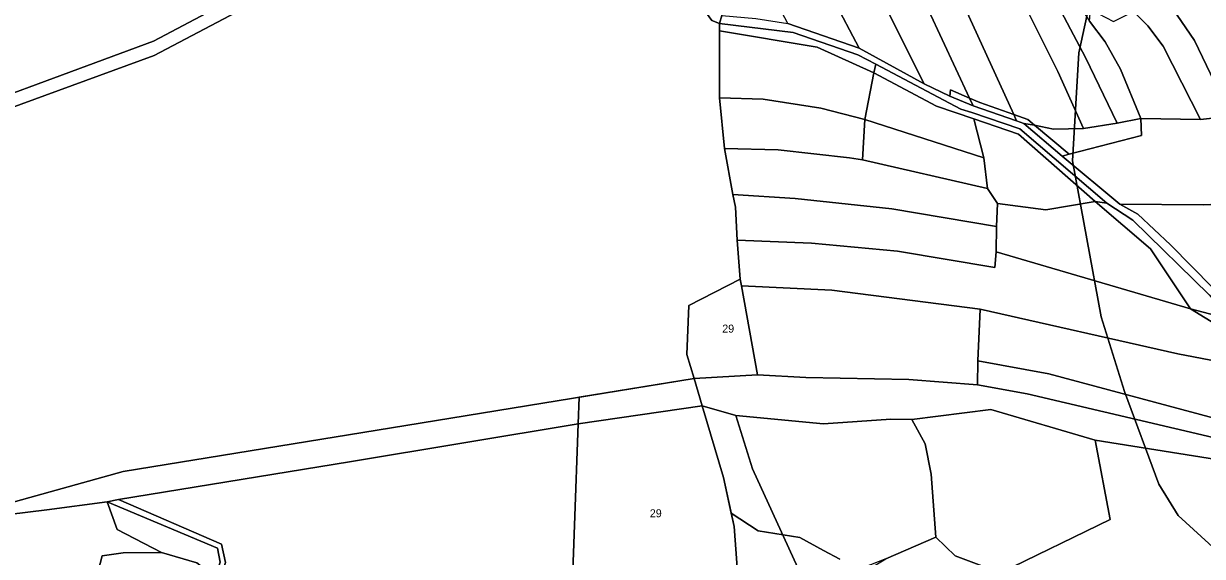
# Model space of a CAD drawing. Extents: x -521261 to -517465, y -1182764 to -1179456.
# Drawn here: x -520500 to -519763, y -1180889 to -1180556 of the extents above; entities that cross this region are included whole.
import ezdxf

# ---------------------------------------------------------------- set-up
doc = ezdxf.new("R2010")
doc.units = 0
for name, color, linetype in [('95560013', 7, 'Continuous'), ('95610013', 7, 'Continuous'), ('95620013', 7, 'Continuous'), ('95640013', 7, 'Continuous'), ('95660013', 7, 'Continuous')]:
    doc.layers.add(name, color=color, linetype=linetype)

msp = doc.modelspace()

# ---------------------------------------------------------------- linework, layer by layer
at = {"layer": '95560013'}
for points in [[(-519926.76, -1180525.85), (-519920.55, -1180526.74), (-519881.21, -1180613), (-519902.42, -1180605.56), (-519908.84, -1180602.74), (-519942.92, -1180529.19)], [(-519879.66, -1180533.88), (-519853.6, -1180586.17), (-519837.56, -1180621.72), (-519856.32, -1180622.11), (-519868.13, -1180619.64), (-519872.32, -1180616.13), (-519881.21, -1180613), (-519920.55, -1180526.74)], [(-519966.95, -1180534.21), (-519937.24, -1180593.79), (-519977.79, -1180571.45), (-519993.87, -1180540.91)], [(-519942.92, -1180529.19), (-519908.84, -1180602.74), (-519920.76, -1180597.55), (-519921.12, -1180601.42), (-519937.24, -1180593.79), (-519966.95, -1180534.21)], [(-519857.1, -1180537.86), (-519836.41, -1180577.26), (-519816.49, -1180618.3), (-519837.56, -1180621.72), (-519853.6, -1180586.17), (-519879.66, -1180533.88)], [(-519993.87, -1180540.91), (-519977.79, -1180571.45), (-520022.38, -1180556.11), (-520025.98, -1180548.95)], [(-519843.08, -1180540.27), (-519833.76, -1180554.68), (-519824.12, -1180567.61), (-519814.57, -1180584.59), (-519801.81, -1180615.54), (-519816.49, -1180618.3), (-519836.41, -1180577.26), (-519857.1, -1180537.86)], [(-520065.13, -1180560.74), (-520004.02, -1180570.89), (-519968.52, -1180586.94), (-519974.16, -1180616.17), (-520001.62, -1180608.95), (-520037.78, -1180603.34), (-520065.1, -1180602.48)], [(-519968.52, -1180586.94), (-519929.38, -1180607.81), (-519906.15, -1180615.63), (-519899.83, -1180640.03), (-519974.16, -1180616.17)], [(-520065.1, -1180602.48), (-520037.78, -1180603.34), (-520001.62, -1180608.95), (-519974.16, -1180616.17), (-519975.68, -1180641.23), (-519983.78, -1180640.12), (-520028.41, -1180635.13), (-520061.92, -1180634.28)], [(-519878.11, -1180625.31), (-519830.39, -1180667.29), (-519861.08, -1180672.47), (-519891.43, -1180668.65), (-519897.52, -1180659.28), (-519899.83, -1180640.03), (-519906.15, -1180615.63)], [(-519816.49, -1180618.3), (-519801.81, -1180615.54), (-519801.28, -1180626.06), (-519846.5, -1180637.75), (-519868.13, -1180619.64), (-519856.32, -1180622.11), (-519837.56, -1180621.72)], [(-519974.16, -1180616.17), (-519899.83, -1180640.03), (-519897.52, -1180659.28), (-519975.68, -1180641.23)], [(-520061.92, -1180634.28), (-520028.41, -1180635.13), (-519983.78, -1180640.12), (-519975.68, -1180641.23), (-519897.52, -1180659.28), (-519891.43, -1180668.65), (-519891.89, -1180682.93), (-519957.26, -1180672.03), (-520017.65, -1180665.4), (-520056.64, -1180662.89)], [(-520017.65, -1180665.4), (-519957.26, -1180672.03), (-519891.89, -1180682.93), (-519892.08, -1180698.83), (-519893.06, -1180708.57), (-519953.8, -1180698.37), (-520007.56, -1180693.31), (-520054.03, -1180691.48), (-520055.03, -1180670.89), (-520056.64, -1180662.89)], [(-519861.08, -1180672.47), (-519830.39, -1180667.29), (-519795.72, -1180696.92), (-519770.67, -1180734.47), (-519892.08, -1180698.83), (-519891.89, -1180682.93), (-519891.43, -1180668.65)], [(-520007.56, -1180693.31), (-519953.8, -1180698.37), (-519893.06, -1180708.57), (-519892.08, -1180698.83), (-519770.67, -1180734.47), (-519752.39, -1180745.68), (-519753.69, -1180767.33), (-519778.68, -1180762.64), (-519902.11, -1180734.59), (-519994.76, -1180722.85), (-520051.3, -1180720.05), (-520052.16, -1180715.87), (-520054.03, -1180691.48)], [(-520051.3, -1180720.05), (-519994.76, -1180722.85), (-519902.11, -1180734.59), (-519903.71, -1180766.9), (-519903.89, -1180781.93), (-519946.67, -1180778.48), (-520011.06, -1180777.29), (-520041.21, -1180775.69)], [(-519902.11, -1180734.59), (-519778.68, -1180762.64), (-519753.69, -1180767.33), (-519755.86, -1180802.82), (-519859.26, -1180774.99), (-519903.71, -1180766.9)], [(-519903.71, -1180766.9), (-519859.26, -1180774.99), (-519755.86, -1180802.82), (-519756.54, -1180814.92), (-519872.76, -1180787.48), (-519903.89, -1180781.93)]]:
    msp.add_lwpolyline(points, close=True, dxfattribs=at)
at = {"layer": '95610013'}
for points in [[(-519787.11, -1180538.74), (-519768.22, -1180566.74), (-519755.66, -1180592.71), (-519747.7, -1180614.18), (-519764.44, -1180616.17), (-519787.86, -1180570.19), (-519797.31, -1180557.63), (-519806.32, -1180548.59), (-519809.29, -1180545.42), (-519790.04, -1180534.46)], [(-519762, -1180533.09), (-519756.87, -1180539.77), (-519746.34, -1180566.13), (-519737.99, -1180583.64), (-519734.67, -1180590.12), (-519723.97, -1180611.09), (-519747.7, -1180614.18), (-519755.66, -1180592.71), (-519768.22, -1180566.74), (-519787.11, -1180538.74), (-519764.17, -1180530.48)], [(-519833.18, -1180547.3), (-519818.8, -1180554.91), (-519806.32, -1180548.59), (-519797.31, -1180557.63), (-519787.86, -1180570.19), (-519764.44, -1180616.17), (-519801.81, -1180615.54), (-519814.57, -1180584.59), (-519824.12, -1180567.61), (-519833.76, -1180554.68)], [(-519764.44, -1180616.17), (-519747.7, -1180614.18), (-519717.59, -1180667.43), (-519762.68, -1180669.48), (-519814.85, -1180668.94), (-519850.9, -1180639.04), (-519846.5, -1180637.75), (-519801.28, -1180626.06), (-519801.81, -1180615.54)], [(-519717.59, -1180667.43), (-519708.21, -1180689.61), (-519692.2, -1180746.98), (-519697.59, -1180747.55), (-519712.21, -1180749.16), (-519717.76, -1180748.91), (-519756.77, -1180721.21), (-519783.25, -1180694.48), (-519803.71, -1180675.31), (-519814.85, -1180668.94), (-519762.68, -1180669.48)], [(-520413.63, -1180886.67), (-520391.57, -1180893.1), (-520380.19, -1180902.05), (-520402.93, -1180971), (-520404.76, -1180971.74), (-520414.45, -1180949.49), (-520429.91, -1180949.77), (-520466.27, -1180947.66), (-520450.85, -1180888.84), (-520437.74, -1180886.84)]]:
    msp.add_lwpolyline(points, close=True, dxfattribs=at)
at = {"layer": '95620013'}
for points in [[(-520561.44, -1180628.41), (-520418.21, -1180576.2), (-520359.3, -1180545.16), (-520250.11, -1180487.13), (-520218.6, -1180468.97), (-520194.59, -1180462.72), (-520147.74, -1180469.38), (-520127.48, -1180474.4), (-520069.86, -1180554.25), (-520065.03, -1180556.21), (-520065.13, -1180560.74), (-520065.1, -1180602.48), (-520061.92, -1180634.28), (-520056.64, -1180662.89), (-520055.03, -1180670.89), (-520054.03, -1180691.48), (-520052.16, -1180715.87), (-520084.17, -1180732.28), (-520085.42, -1180763.05), (-520080.76, -1180777.95), (-520260.96, -1180807.27), (-520437.72, -1180836.09), (-520517.73, -1180858.28)], [(-520267.22, -1180487.01), (-520418.64, -1180567.25), (-520579.89, -1180626.79)]]:
    msp.add_lwpolyline(points, dxfattribs=at)
for points in [[(-520153.4, -1180806.35), (-520157.92, -1180932.93), (-520196.52, -1180926.36), (-520199.57, -1180927.79), (-520202.96, -1180943.49), (-520212.94, -1180946.42), (-520219.04, -1180948.87), (-520227.61, -1180952.85), (-520260.64, -1180952.48), (-520300.29, -1180947.88), (-520344.99, -1180950.96), (-520344.3, -1180943.96), (-520347.18, -1180922.08), (-520360, -1180918.29), (-520377.28, -1180904.27), (-520373.63, -1180892.94), (-520376.27, -1180881.41), (-520440.58, -1180853.57), (-520296.21, -1180829.93)], [(-520447.63, -1180855.08), (-520441.44, -1180872.23), (-520413.63, -1180886.67), (-520437.74, -1180886.84), (-520450.85, -1180888.84), (-520466.27, -1180947.66), (-520479.73, -1180952.5), (-520490.67, -1180954.03), (-520505.09, -1180945.85), (-520508.85, -1180907.38), (-520510.51, -1180896.3), (-520514.96, -1180895.18), (-520522.73, -1180871.37), (-520521.14, -1180864.38), (-520485.24, -1180860)], [(-520441.44, -1180872.23), (-520447.63, -1180855.08), (-520378.72, -1180883.92), (-520376.96, -1180892.63), (-520380.19, -1180902.05), (-520391.57, -1180893.1), (-520413.63, -1180886.67)]]:
    msp.add_lwpolyline(points, close=True, dxfattribs=at)
at = {"layer": '95640013'}
for points in [[(-520579.89, -1180626.79), (-520418.64, -1180567.25), (-520267.22, -1180487.01), (-520224.7, -1180457.68), (-520218.82, -1180457.68), (-520195.07, -1180457.1), (-520147.94, -1180463.58), (-520122.8, -1180471.55), (-520063.47, -1180551.19), (-520042.35, -1180553.05), (-520022.38, -1180556.11), (-519977.79, -1180571.45), (-519937.24, -1180593.79), (-519921.12, -1180601.42), (-519906.63, -1180607.48), (-519879.5, -1180616.96), (-519874.81, -1180618.65), (-519850.9, -1180639.04), (-519814.85, -1180668.94), (-519803.71, -1180675.31), (-519783.25, -1180694.48), (-519756.77, -1180721.21)], [(-519759.06, -1180725.67), (-519806.67, -1180679.04), (-519823.08, -1180668.31), (-519877.33, -1180621.85), (-519907.42, -1180611.79), (-519914.26, -1180609.63), (-519967.45, -1180581.52), (-519978.62, -1180575.67), (-520019.07, -1180561.78), (-520065.03, -1180556.21), (-520069.86, -1180554.25), (-520127.48, -1180474.4), (-520147.74, -1180469.38), (-520194.59, -1180462.72), (-520218.6, -1180468.97), (-520250.11, -1180487.13), (-520359.3, -1180545.16), (-520418.21, -1180576.2), (-520561.44, -1180628.41)], [(-519762.65, -1180910.2), (-519780.23, -1180911.25), (-519803.42, -1180920.5), (-519828.85, -1180932.73), (-519852.45, -1180947.32), (-519857.68, -1180946.63), (-519859.11, -1180944.04), (-519877.24, -1180908.93), (-519889.4, -1180899.42), (-519820.97, -1180866.09), (-519830.34, -1180816.46), (-519754.46, -1180828.52)]]:
    msp.add_lwpolyline(points, dxfattribs=at)
for points in [[(-520065.03, -1180556.21), (-520019.07, -1180561.78), (-519978.62, -1180575.67), (-519967.45, -1180581.52), (-519968.52, -1180586.94), (-520004.02, -1180570.89), (-520065.13, -1180560.74)], [(-519968.52, -1180586.94), (-519967.45, -1180581.52), (-519914.26, -1180609.63), (-519907.42, -1180611.79), (-519877.33, -1180621.85), (-519823.08, -1180668.31), (-519830.39, -1180667.29), (-519878.11, -1180625.31), (-519906.15, -1180615.63), (-519929.38, -1180607.81)], [(-519920.76, -1180597.55), (-519908.84, -1180602.74), (-519906.63, -1180607.48), (-519921.12, -1180601.42)], [(-519902.42, -1180605.56), (-519881.21, -1180613), (-519879.5, -1180616.96), (-519906.63, -1180607.48), (-519908.84, -1180602.74)], [(-519872.32, -1180616.13), (-519868.13, -1180619.64), (-519874.81, -1180618.65), (-519879.5, -1180616.96), (-519881.21, -1180613)], [(-519874.81, -1180618.65), (-519868.13, -1180619.64), (-519846.5, -1180637.75), (-519850.9, -1180639.04)], [(-519830.39, -1180667.29), (-519823.08, -1180668.31), (-519806.67, -1180679.04), (-519759.06, -1180725.67), (-519746.21, -1180740.96), (-519770.67, -1180734.47), (-519795.72, -1180696.92)], [(-520052.16, -1180715.87), (-520051.3, -1180720.05), (-520041.21, -1180775.69), (-520080.76, -1180777.95), (-520085.42, -1180763.05), (-520084.17, -1180732.28)], [(-519770.67, -1180734.47), (-519746.21, -1180740.96), (-519730.77, -1180757.97), (-519752.39, -1180745.68)], [(-520011.06, -1180777.29), (-519946.67, -1180778.48), (-519903.89, -1180781.93), (-519872.76, -1180787.48), (-519756.54, -1180814.92), (-519712.86, -1180822.81), (-519712.22, -1180850.29), (-519724.46, -1180847.03), (-519724.95, -1180841.1), (-519739.68, -1180829.86), (-519754.46, -1180828.52), (-519830.34, -1180816.46), (-519895.53, -1180797.23), (-519944.79, -1180803.65), (-519957.95, -1180803.28), (-520000.15, -1180806.24), (-520054.72, -1180801.07), (-520075.86, -1180795.03), (-520080.76, -1180777.95), (-520041.21, -1180775.69)], [(-520080.76, -1180777.95), (-520075.86, -1180795.03), (-520153.4, -1180806.35), (-520296.21, -1180829.93), (-520440.58, -1180853.57), (-520447.63, -1180855.08), (-520485.24, -1180860), (-520521.14, -1180864.38), (-520532.28, -1180856.24), (-520565.24, -1180830.11), (-520584.27, -1180823.22), (-520567.99, -1180819.26), (-520561.06, -1180820.59), (-520517.73, -1180858.28), (-520437.72, -1180836.09), (-520260.96, -1180807.27)], [(-520075.86, -1180795.03), (-520062.43, -1180839.83), (-520055.89, -1180870.36), (-520052.08, -1180921.54), (-520063.22, -1180921.42), (-520109.27, -1180947.28), (-520129.83, -1180952.33), (-520148.15, -1180951.58), (-520165.05, -1180947.64), (-520157.92, -1180932.93), (-520153.4, -1180806.35)], [(-520075.86, -1180795.03), (-520054.72, -1180801.07), (-520044.44, -1180834.39), (-520009.14, -1180911.27), (-520027.64, -1180915.53), (-520052.08, -1180921.54), (-520055.89, -1180870.36), (-520062.43, -1180839.83)], [(-519944.79, -1180803.65), (-519895.53, -1180797.23), (-519830.34, -1180816.46), (-519820.97, -1180866.09), (-519889.4, -1180899.42), (-519917.75, -1180888.83), (-519929.88, -1180877.1), (-519932.71, -1180837.71), (-519936.58, -1180818.81)], [(-519957.95, -1180803.28), (-519944.79, -1180803.65), (-519936.58, -1180818.81), (-519932.71, -1180837.71), (-519929.88, -1180877.1), (-519961.16, -1180890.66), (-519989.88, -1180901.85), (-520009.14, -1180911.27), (-520044.44, -1180834.39), (-520054.72, -1180801.07), (-520000.15, -1180806.24)], [(-520447.63, -1180855.08), (-520440.58, -1180853.57), (-520376.27, -1180881.41), (-520373.63, -1180892.94), (-520377.28, -1180904.27), (-520380.19, -1180902.05), (-520376.96, -1180892.63), (-520378.72, -1180883.92)], [(-519917.75, -1180888.83), (-519889.4, -1180899.42), (-519877.24, -1180908.93), (-519859.11, -1180944.04), (-519857.68, -1180946.63), (-519913.83, -1180971.76), (-519924.17, -1180970.12), (-519933.74, -1180965.29), (-519970.64, -1180971.8), (-520002.63, -1180979.16), (-520027.64, -1180915.53), (-520009.14, -1180911.27), (-519994.33, -1180910.58), (-519961.16, -1180890.66), (-519929.88, -1180877.1)]]:
    msp.add_lwpolyline(points, close=True, dxfattribs=at)
at = {"layer": '95660013'}
for points in [[(-519739, -1180397), (-519775, -1180405), (-519786.5, -1180414), (-519802.5, -1180437), (-519821, -1180484.5), (-519840.5, -1180574.5), (-519844.5, -1180642), (-519826.5, -1180739.5), (-519812, -1180786), (-519790.5, -1180844), (-519778.5, -1180863.5), (-519754.5, -1180885.5)], [(-519754.5, -1180885.5), (-519778.5, -1180863.5), (-519790.5, -1180844), (-519812, -1180786), (-519826.5, -1180739.5), (-519844.5, -1180642), (-519840.5, -1180574.5), (-519821, -1180484.5), (-519802.5, -1180437), (-519786.5, -1180414), (-519775, -1180405), (-519739, -1180397)], [(-520063.47, -1180551.19), (-520065.03, -1180556.21), (-520065.13, -1180560.74), (-520065.1, -1180602.48), (-520061.92, -1180634.28), (-520056.64, -1180662.89), (-520055.03, -1180670.89), (-520054.03, -1180691.48), (-520052.16, -1180715.87), (-520084.17, -1180732.28), (-520085.42, -1180763.05), (-520080.76, -1180777.95), (-520152.8, -1180789.67), (-520153.4, -1180806.35), (-520157.92, -1180932.93)], [(-519989.85, -1180890.87), (-520000, -1180885.4), (-520014.83, -1180877.4), (-520040.78, -1180873.08), (-520057.64, -1180862.17), (-520062.43, -1180839.83), (-520075.86, -1180795.03), (-520080.76, -1180777.95), (-520041.21, -1180775.69), (-520051.3, -1180720.05), (-520052.16, -1180715.87), (-520054.03, -1180691.48), (-520055.03, -1180670.89), (-520056.64, -1180662.89), (-520061.92, -1180634.28), (-520065.1, -1180602.48), (-520065.13, -1180560.74), (-520065.03, -1180556.21), (-520063.47, -1180551.19)], [(-520052.08, -1180921.54), (-520055.89, -1180870.36), (-520057.64, -1180862.17), (-520040.78, -1180873.08), (-520014.83, -1180877.4), (-520000, -1180885.4), (-519989.85, -1180890.87)], [(-520391.57, -1180893.1), (-520413.63, -1180886.67), (-520437.74, -1180886.84), (-520450.85, -1180888.84), (-520466.27, -1180947.66)], [(-520466.27, -1180947.66), (-520450.85, -1180888.84), (-520437.74, -1180886.84), (-520413.63, -1180886.67), (-520391.57, -1180893.1)]]:
    msp.add_lwpolyline(points, dxfattribs=at)
for points in [[(-520080.76, -1180777.95), (-520085.42, -1180763.05), (-520084.17, -1180732.28), (-520052.16, -1180715.87), (-520051.3, -1180720.05), (-520041.21, -1180775.69)], [(-520153.4, -1180806.35), (-520152.8, -1180789.67), (-520080.76, -1180777.95), (-520075.86, -1180795.03), (-520062.43, -1180839.83), (-520055.89, -1180870.36), (-520052.08, -1180921.54), (-520063.22, -1180921.42), (-520109.27, -1180947.28), (-520129.83, -1180952.33), (-520148.15, -1180951.58), (-520165.05, -1180947.64), (-520157.92, -1180932.93)]]:
    msp.add_lwpolyline(points, close=True, dxfattribs=at)

# ---------------------------------------------------------------- texts
for p in [(-520063.32, -1180749.27), (-520108.57, -1180864.68)]:
    msp.add_text('29', height=5, rotation=0, dxfattribs=at).set_placement(p)

doc.saveas('drawing.dxf')
